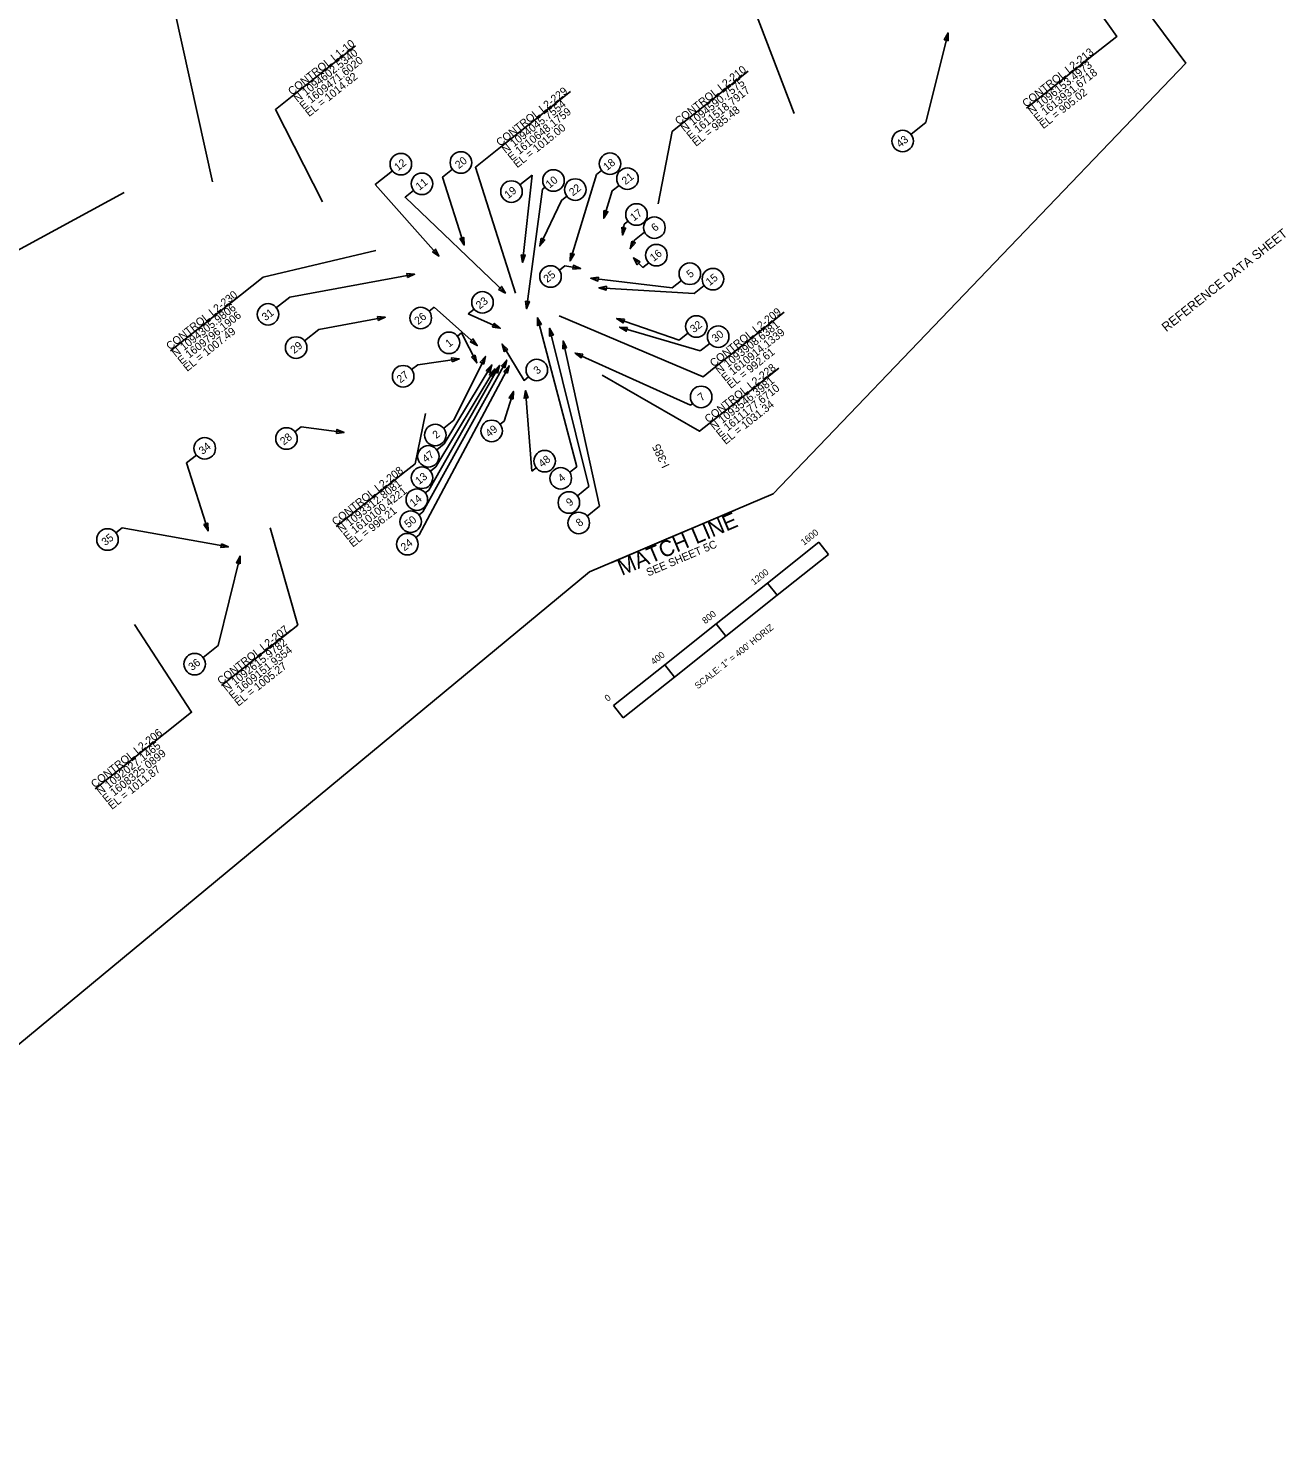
# Model space of a CAD drawing. Extents: x 1600294 to 1616097, y 1087057 to 1101809.
# Drawn here: x 1607677 to 1615346, y 1087057 to 1095661 of the extents above; entities that cross this region are included whole.
import ezdxf

# ---------------------------------------------------------------- set-up
doc = ezdxf.new("R2010")
doc.units = 0
for name, color, linetype in [('LABEL', 7, 'Continuous'), ('Level 24', 7, 'Continuous'), ('Level 6', 7, 'Continuous'), ('Plan_Clip', 7, 'Continuous'), ('RD_SHT_MatchLine', 7, 'Continuous'), ('RD_SHT_TX', 7, 'Continuous'), ('RD_TX_Misc1', 7, 'Continuous'), ('RD_TX_RoadID', 7, 'Continuous')]:
    doc.layers.add(name, color=color, linetype=linetype)

msp = doc.modelspace()

# ---------------------------------------------------------------- linework, layer by layer
at = {"layer": 'LABEL'}
for p, q in [((1610675.6, 1094706.5), (1610750, 1094765.8)), ((1610813.3, 1094679.8), (1610715.8, 1093950.8)), ((1610828.8, 1094692.1), (1610813.3, 1094679.8)), ((1611374.6, 1094369.3), (1611348.7, 1094316.9)), ((1611436.2, 1094418.4), (1611374.6, 1094369.3)), ((1611738.4, 1094044.2), (1611157.4, 1094079.7)), ((1611799.7, 1094092.9), (1611738.4, 1094044.2)), ((1610122.5, 1093935.6), (1610153.7, 1093960.4)), ((1610153.7, 1093960.4), (1610415, 1093727.2)), ((1610395.8, 1093949.1), (1610359.4, 1093920.2)), ((1610359.4, 1093920.2), (1610556, 1093832)), ((1611022.2, 1092988.1), (1610782.7, 1093896.2)), ((1611096.2, 1092866.9), (1610856.6, 1093831.9)), ((1611646.2, 1093759.1), (1611265.1, 1093891.3)), ((1611775.3, 1093694), (1611283.7, 1093839.1)), ((1610294.8, 1093784.6), (1610318.6, 1093803.5)), ((1610412.7, 1093621.2), (1610318.6, 1093803.5)), ((1611161.9, 1092747), (1610938.7, 1093755.1)), ((1611700.5, 1093802.4), (1611646.2, 1093759.1)), ((1611833.3, 1093740.1), (1611775.3, 1093694)), ((1610465.5, 1093660.4), (1610273.4, 1093272.3)), ((1611716.9, 1093363.1), (1611011.8, 1093681.4)), ((1610610, 1093604), (1610062.2, 1092574)), ((1610595.7, 1093637.9), (1610083.9, 1092712.9)), ((1610551.9, 1093605.3), (1610119.9, 1092845.6)), ((1610523.4, 1093584.1), (1610162.9, 1092988.3)), ((1610504.7, 1093608.7), (1610214, 1093128.2)), ((1610635.6, 1093447.4), (1610578.6, 1093266.3)), ((1610709.3, 1093452.6), (1610748.8, 1092960.4)), ((1611729.2, 1093372.9), (1611716.9, 1093363.1)), ((1610210.9, 1093222.5), (1610273.4, 1093272.3)), ((1610554.8, 1093247.4), (1610578.6, 1093266.3)), ((1610168.9, 1093092.2), (1610214, 1093128.2)), ((1610129.8, 1092962), (1610162.9, 1092988.3)), ((1610775.3, 1092981.5), (1610748.8, 1092960.4)), ((1610979.1, 1092954.4), (1611022.2, 1092988.1)), ((1610098.6, 1092828.7), (1610119.9, 1092845.6)), ((1611025.8, 1092811), (1611096.2, 1092866.9)), ((1610060.8, 1092694.5), (1610083.9, 1092712.9)), ((1611085.9, 1092686.5), (1611161.9, 1092747)), ((1610040.9, 1092557.1), (1610062.2, 1092574))]:
    msp.add_line(p, q, dxfattribs=at)
for points in [[(1613060.9, 1095014.5), (1613151.9, 1095086.9), (1613286.5, 1095632.8)], [(1609898.1, 1094791.8), (1609793.6, 1094708.6), (1610181.6, 1094272.4)], [(1610264.4, 1094801.7), (1610204, 1094753.7), (1610335.8, 1094339)], [(1610750, 1094765.8), (1610691.3, 1094233.7)], [(1611173.5, 1094794.4), (1611142.1, 1094769.4), (1610981.7, 1094243.3)], [(1611280.1, 1094703.3), (1611239, 1094670.6), (1611186.4, 1094502.7)], [(1610026.7, 1094672.1), (1609975.1, 1094631.1), (1610587.5, 1094046.7)], [(1610961.8, 1094636.8), (1610929.9, 1094611.5), (1610796.1, 1094334.1)], [(1611335.2, 1094484.8), (1611312.1, 1094466.4), (1611300.4, 1094400.3)], [(1611461.7, 1094231.1), (1611426.1, 1094202.8), (1611367.9, 1094261.1)], [(1610916.3, 1094185.5), (1610950.5, 1094212.7), (1611045.2, 1094195.7)], [(1609191, 1093957.9), (1609272.5, 1094022.7), (1610033.1, 1094161.7)], [(1611660.5, 1094123.7), (1611604.1, 1094078.9), (1611107.4, 1094137.6)], [(1609362.3, 1093755.4), (1609450.1, 1093825.3), (1609854.6, 1093899.6)], [(1610727.7, 1093536), (1610701.1, 1093514.8), (1610567.2, 1093736)], [(1610015.3, 1093580.1), (1610052.9, 1093609.9), (1610305.6, 1093645.9)], [(1609303.5, 1093201), (1609341.3, 1093231.1), (1609603.4, 1093197.1)], [(1608702.3, 1093059.5), (1608641.9, 1093011.5), (1608773.6, 1092596.8)], [(1608211.9, 1092585.2), (1608249.8, 1092615.3), (1608897.8, 1092499.8)], [(1608743.7, 1091825.8), (1608834.6, 1091898.2), (1608969.3, 1092444)]]:
    msp.add_lwpolyline(points, dxfattribs=at)
for points in [[(1613287.5, 1095585.2), (1613286.5, 1095632.8), (1613263.6, 1095591.1)], [(1611188.4, 1094550.2), (1611186.4, 1094502.7), (1611211.9, 1094542.8)], [(1611296.3, 1094447.7), (1611300.4, 1094400.3), (1611320.5, 1094443.4)], [(1610310.1, 1094379), (1610335.8, 1094339), (1610333.6, 1094386.5)], [(1610805, 1094380.8), (1610796.1, 1094334.1), (1610827.1, 1094370.1)], [(1611358, 1094363.6), (1611348.7, 1094316.9), (1611380.1, 1094352.7)], [(1610142, 1094298.6), (1610181.6, 1094272.4), (1610160.3, 1094314.9)], [(1610684.1, 1094280.7), (1610691.3, 1094233.7), (1610708.6, 1094278)], [(1610983.3, 1094290.8), (1610981.7, 1094243.3), (1611006.8, 1094283.7)], [(1611409, 1094237.3), (1611367.9, 1094261.1), (1611391.6, 1094219.9)], [(1609990.1, 1094141.3), (1610033.1, 1094161.7), (1609985.7, 1094165.5)], [(1610997.9, 1094191.7), (1611045.2, 1094195.7), (1611002.2, 1094215.9)], [(1610545.8, 1094069.5), (1610587.5, 1094046.7), (1610562.7, 1094087.3)], [(1611154.4, 1094144.4), (1611107.4, 1094137.6), (1611151.6, 1094120)], [(1611204, 1094089.2), (1611157.4, 1094079.7), (1611202.5, 1094064.7)], [(1610709.6, 1093997.9), (1610715.8, 1093950.8), (1610734, 1093994.6)], [(1609811.7, 1093879.2), (1609854.6, 1093899.6), (1609807.2, 1093903.4)], [(1610509, 1093839.6), (1610556, 1093832), (1610519.1, 1093862)], [(1610806.3, 1093854.9), (1610782.7, 1093896.2), (1610782.5, 1093848.7)], [(1610879.6, 1093790.3), (1610856.6, 1093831.9), (1610855.8, 1093784.3)], [(1611312.5, 1093887.9), (1611265.1, 1093891.3), (1611304.4, 1093864.6)], [(1611331.2, 1093837.9), (1611283.7, 1093839.1), (1611324.2, 1093814.3)], [(1610372.5, 1093748.6), (1610415, 1093727.2), (1610388.9, 1093766.9)], [(1610601.5, 1093703.1), (1610567.2, 1093736), (1610580.5, 1093690.4)], [(1610960.7, 1093712.9), (1610938.7, 1093755.1), (1610936.6, 1093707.6)], [(1610261.9, 1093627.2), (1610305.6, 1093645.9), (1610258.4, 1093651.6)], [(1610380.7, 1093656.3), (1610412.7, 1093621.2), (1610402.6, 1093667.6)], [(1610456.2, 1093613.8), (1610465.5, 1093660.4), (1610434.1, 1093624.7)], [(1611058.7, 1093673.7), (1611011.8, 1093681.4), (1611048.6, 1093651.3)], [(1610491.5, 1093563), (1610504.7, 1093608.7), (1610470.5, 1093575.8)], [(1610510.1, 1093538.5), (1610523.4, 1093584.1), (1610489.1, 1093551.2)], [(1610539.9, 1093559.3), (1610551.9, 1093605.3), (1610518.5, 1093571.5)], [(1610584.3, 1093591.8), (1610595.7, 1093637.9), (1610562.7, 1093603.7)], [(1610599.3, 1093557.7), (1610610, 1093604), (1610577.6, 1093569.2)], [(1610633.5, 1093400), (1610635.6, 1093447.4), (1610610, 1093407.3)], [(1610725.3, 1093407.8), (1610709.3, 1093452.6), (1610700.8, 1093405.8)], [(1609556.3, 1093190.8), (1609603.4, 1093197.1), (1609559.5, 1093215.2)], [(1608748, 1092636.8), (1608773.6, 1092596.8), (1608771.5, 1092644.2)], [(1608970.2, 1092396.5), (1608969.3, 1092444), (1608946.3, 1092402.4)]]:
    msp.add_lwpolyline(points, close=True, dxfattribs=at)
for centre in [(1613009.5, 1094973.6), (1609949.6, 1094832.7), (1610315.8, 1094842.6), (1611224.9, 1094835.3), (1610078.1, 1094713), (1610880.2, 1094733), (1611331.5, 1094744.2), (1610624.1, 1094665.6), (1611013.3, 1094677.7), (1611386.6, 1094525.7), (1611496, 1094445.6), (1611508.1, 1094277.7), (1610862.4, 1094147.9), (1611711.9, 1094164.6), (1611852.7, 1094131.8), (1610447.2, 1093990), (1609139.6, 1093917), (1610071, 1093894.7), (1611751.9, 1093843.3), (1611884.7, 1093781), (1609310.9, 1093714.5), (1610243.4, 1093743.7), (1609963.5, 1093539.7), (1610778.5, 1093578.1), (1611780.7, 1093413.8), (1609252, 1093160.1), (1610159.5, 1093181.6), (1610503.4, 1093206.5), (1608753.7, 1093100.4), (1610117.4, 1093051.3), (1610826.7, 1093022.4), (1610078.4, 1092921.1), (1610924.7, 1092917.6), (1610047.2, 1092787.8), (1610974.3, 1092770.1), (1610009.3, 1092653.6), (1611034.5, 1092645.6), (1608160.5, 1092544.3), (1609989.5, 1092516.1), (1608692.2, 1091784.9)]:
    msp.add_circle(centre, 65.7, dxfattribs=at)
at = {"layer": 'Level 24'}
msp.add_lwpolyline([(1608855.5, 1092518.8), (1608897.8, 1092499.8), (1608851.5, 1092496.6)], close=True, dxfattribs=at)
at = {"layer": 'Plan_Clip'}
msp.add_lwpolyline([(1600293.9, 1092641.5), (1602343.7, 1094579.4), (1605167, 1096872.5), (1609119.4, 1099879.5), (1609257.5, 1099698.1), (1610590.9, 1100773.5), (1613569.3, 1097017.7), (1614735.8, 1095448.6), (1612219.9, 1092822.8), (1611099.3, 1092347), (1604705.4, 1087056.6)], close=True, dxfattribs=at)
at = {"layer": 'RD_SHT_MatchLine'}
for q in [(1611982.8, 1092722.1), (1611236.7, 1092405.3)]:
    msp.add_line((1611568.2, 1092546), q, dxfattribs=at)
at = {"layer": 'RD_SHT_TX'}
for p, q in [((1609673.6, 1095554.4), (1609287.7, 1095247.5)), ((1614184.5, 1095506.8), (1613765.6, 1095173.6)), ((1612067.3, 1095400), (1611647.5, 1095066.1)), ((1610983.5, 1095274.7), (1610557.2, 1094935.6)), ((1608971, 1094033.5), (1608544.4, 1093694.2)), ((1612286.4, 1093929.4), (1611860, 1093590.3)), ((1612254.5, 1093588.6), (1611828, 1093249.4)), ((1609981.5, 1092962.3), (1609555, 1092623.1)), ((1609281.6, 1091992), (1608856.1, 1091653.6)), ((1608512.9, 1091363.9), (1608085.3, 1091023.9))]:
    msp.add_line(p, q, dxfattribs=at)
for points in [[(1611999.8, 1096597.4), (1611839.6, 1096470), (1612347.5, 1095141.9)], [(1614184.5, 1095506.8), (1614316.5, 1095611.8), (1613931.7, 1096153.5)], [(1608687.5, 1095855.7), (1608570.6, 1095762.7), (1608800.8, 1094724.6)], [(1609287.7, 1095247.5), (1609184.9, 1095165.7), (1609471.6, 1094602.5)], [(1611647.5, 1095066.1), (1611604.6, 1095032), (1611518.8, 1094590.8)], [(1610557.2, 1094935.6), (1610404.2, 1094813.9), (1610648.2, 1094045.8)], [(1607126.6, 1094016.7), (1607235.9, 1094103.6), (1608262.6, 1094659.5)], [(1608971, 1094033.5), (1609109.7, 1094143.9), (1609796.2, 1094306)], [(1611860, 1093590.3), (1611793.3, 1093537.2), (1610914.1, 1093908.6)], [(1611828, 1093249.4), (1611771.7, 1093204.6), (1611177.7, 1093546.4)], [(1609981.5, 1092962.3), (1610036.9, 1093006.4), (1610100.4, 1093312.8)], [(1608856.1, 1091653.6), (1609320.7, 1092023.1), (1609151.9, 1092616)], [(1608512.9, 1091363.9), (1608673.7, 1091491.9), (1608325.1, 1092027.1)]]:
    msp.add_lwpolyline(points, dxfattribs=at)
at = {"layer": 'RD_TX_Misc1'}
for p, q in [((1612185.2, 1092279.1), (1612498.3, 1092528.2)), ((1612244.7, 1092204.3), (1612557.8, 1092453.3)), ((1612498.3, 1092528.2), (1612557.8, 1092453.3)), ((1612185.2, 1092279.1), (1611872.2, 1092030.1)), ((1612244.7, 1092204.3), (1612185.2, 1092279.1)), ((1611931.7, 1091955.3), (1612244.7, 1092204.3)), ((1611559.2, 1091781.1), (1611872.2, 1092030.1)), ((1611872.2, 1092030.1), (1611931.7, 1091955.3)), ((1611618.7, 1091706.3), (1611931.7, 1091955.3)), ((1611559.2, 1091781.1), (1611246.1, 1091532.1)), ((1611618.7, 1091706.3), (1611559.2, 1091781.1)), ((1611305.6, 1091457.3), (1611618.7, 1091706.3)), ((1611246.1, 1091532.1), (1611305.6, 1091457.3))]:
    msp.add_line(p, q, dxfattribs=at)

# ---------------------------------------------------------------- texts
at = {"layer": 'LABEL'}
for s, height, p in [('43', 47.52, (1612994, 1094930.9)), ('12', 47.52, (1609932.4, 1094788.6)), ('20', 47.52, (1610302.7, 1094801.8)), ('18', 47.52, (1611206.9, 1094790.6)), ('21', 47.52, (1611319.5, 1094704.3)), ('11', 47.52, (1610063, 1094670.6)), ('19', 47.52, (1610604.6, 1094619.7)), ('10', 47.52, (1610856.2, 1094683.5)), ('22', 47.52, (1610998.2, 1094635.4)), ('17', 47.52, (1611371, 1094482.9)), ('6', 47.5, (1611499.5, 1094419)), ('16', 47.52, (1611491.3, 1094236.3)), ('25', 47.52, (1610842.5, 1094107.1)), ('5', 47.5, (1611714.4, 1094136.2)), ('15', 47.52, (1611832.4, 1094088.6)), ('23', 47.52, (1610430.4, 1093946.3)), ('31', 47.52, (1609124.8, 1093874.9)), ('26', 47.52, (1610054.9, 1093851.5)), ('32', 47.52, (1611736.5, 1093801.8)), ('30', 47.52, (1611868.3, 1093744.1)), ('29', 47.52, (1609299, 1093674.7)), ('1', 47.5, (1610243.7, 1093713.5)), ('27', 47.52, (1609947.1, 1093495.4)), ('3', 47.5, (1610781.6, 1093548.5)), ('7', 47.5, (1611783.2, 1093385.4)), ('49', 47.52, (1610488.5, 1093165.5)), ('34', 47.52, (1608740.5, 1093059.6)), ('28', 47.52, (1609235.9, 1093116.9)), ('2', 47.5, (1610165.4, 1093155.9)), ('47', 47.52, (1610102.5, 1093010.3)), ('48', 47.52, (1610811.8, 1092981.3)), ('13', 47.52, (1610060.6, 1092876.6)), ('4', 47.5, (1610930.1, 1092891.5)), ('14', 47.52, (1610027, 1092741.3)), ('9', 47.5, (1610979.8, 1092744)), ('50', 47.52, (1609994.4, 1092612.6)), ('8', 47.5, (1611039.9, 1092619.6)), ('35', 47.52, (1608147.3, 1092503.5)), ('24', 47.52, (1609971.7, 1092471.6)), ('36', 47.52, (1608676.7, 1091742.2))]:
    msp.add_text(s, height=height, rotation=38.4995, dxfattribs=at).set_placement(p)
at = {"layer": 'Level 6'}
msp.add_text('REFERENCE DATA SHEET', height=55.867, rotation=38.50113, dxfattribs=at).set_placement((1614617.5, 1093808.1))
at = {"layer": 'RD_SHT_MatchLine'}
for s, height, p in [('MATCH LINE ', 96, (1611297.1, 1092322.3)), ('SEE SHEET 5C', 48, (1611458.5, 1092318.8))]:
    msp.add_text(s, height=height, rotation=23.00726, dxfattribs=at).set_placement(p)
at = {"layer": 'RD_SHT_TX'}
for s, p in [('CONTROL L1-10', (1609285.3, 1095250.6)), ('N 1094602.5340', (1609320.1, 1095206.8)), ('E 1609471.6020', (1609355, 1095163)), ('CONTROL L2-213', (1613763.1, 1095176.7)), ('N 1096153.4973', (1613797.9, 1095132.9)), ('EL = 1014.82', (1609389.8, 1095119.1)), ('CONTROL L2-210', (1611645, 1095069.2)), ('E 1613931.6718', (1613832.8, 1095089.1)), ('CONTROL L2-229', (1610554.7, 1094938.7)), ('N 1094590.7575', (1611679.9, 1095025.4)), ('E 1611518.7917', (1611714.7, 1094981.6)), ('EL = 905.02', (1613867.7, 1095045.3)), ('N 1094045.7554', (1610589.5, 1094894.9)), ('E 1610648.1759', (1610624.4, 1094851.1)), ('EL = 985.48', (1611749.6, 1094937.8)), ('EL = 1015.00', (1610659.3, 1094807.2)), ('CONTROL L2-230', (1608542, 1093697.4)), ('N 1094305.9806', (1608576.8, 1093653.5)), ('E 1609796.1906', (1608611.7, 1093609.7)), ('CONTROL L2-209', (1611857.5, 1093593.4)), ('EL = 1007.49', (1608646.5, 1093565.9)), ('N 1093908.6381', (1611892.4, 1093549.6)), ('E 1610914.1339', (1611927.3, 1093505.8)), ('EL = 992.61', (1611962.1, 1093461.9)), ('CONTROL L2-228', (1611825.5, 1093252.5)), ('N 1093546.3981', (1611860.4, 1093208.7)), ('E 1611177.6710', (1611895.2, 1093164.9)), ('EL = 1031.34', (1611930.1, 1093121)), ('CONTROL L2-208', (1609552.5, 1092626.2)), ('N 1093312.8081', (1609587.4, 1092582.4)), ('E 1610100.4221', (1609622.3, 1092538.6)), ('EL = 996.21', (1609657.1, 1092494.8)), ('CONTROL L2-207', (1608853.7, 1091656.7)), ('N 1092615.9782', (1608888.6, 1091612.9)), ('E 1609151.9354', (1608923.4, 1091569.1)), ('EL = 1005.27', (1608958.3, 1091525.3)), ('CONTROL L2-206', (1608083.3, 1091027.3)), ('N 1092027.1465', (1608118.1, 1090983.5)), ('E 1608325.0899', (1608153, 1090939.7)), ('EL = 1011.87', (1608187.8, 1090895.8))]:
    msp.add_text(s, height=48, rotation=38.4995, dxfattribs=at).set_placement(p)
at = {"layer": 'RD_TX_Misc1'}
for s, p in [('1600', (1612408, 1092506.1)), ('1200', (1612104, 1092264.3)), ('800', (1611806.5, 1092027.7)), ('SCALE: 1" = 400\' HORIZ', (1611760.5, 1091630.7)), ('400', (1611493.5, 1091778.7)), ('0', (1611211.5, 1091554.4))]:
    msp.add_text(s, height=40, rotation=38.50113, dxfattribs=at).set_placement(p)
at = {"layer": 'RD_TX_RoadID'}
msp.add_text('I-385', height=50, rotation=115.11059, dxfattribs=at).set_placement((1611589.9, 1092994.6))

doc.saveas('drawing.dxf')
